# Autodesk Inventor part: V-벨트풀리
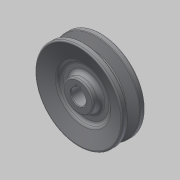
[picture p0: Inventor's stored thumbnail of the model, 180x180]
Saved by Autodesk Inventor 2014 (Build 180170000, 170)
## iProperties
Created: 2016-08
Part Number: V-벨트풀리
Material: 알루미늄 6061
Document SubType Name: Modeling
Designer: mduedu
Density: 2.71 g/cm^3
Appearance: Default
Author: mduedu
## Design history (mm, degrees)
sketch "스케치1"
  geometry: L1 (0, 9.5)-(0, -9.5); L2 (0, 9.5)-(35, 9.5); L3 (35, 9.5)-(35, 4.825); L4 (35, 4.825)-(26, 2.074); L5 (26, 2.074)-(26, 0); L6 (0, 0)-(26, 0); L7 (0, -9.5)-(35, -9.5); L8 (35, -9.5)-(35, -4.825); L9 (35, -4.825)-(26, -2.074); L10 (26, -2.074)-(26, 0); L11 (32.3, 9.5)-(32.3, -9.5); 3 further points
  constraints: 22 end point, 6 point on line, 4 perpendicular, 3 symmetric about line, 1 coincident, 1 horizontal alignment, 1 midpoint, 1 parallel, 1 vertical
  dimensions: "d0" = 19 distance of L1.start L1.end; "d2" = 70 diameter of L8 L1; "d4" = 6.3 distance between parallel lines of L10 L11; "d5" = 2.7 distance between parallel lines of L11 L8; "d6" = 8 distance of point (32.3, -4) point (32.3, 4); "d7" = 34 deg angle of L9 L4
revolve "회전1" sketch "스케치1" stored, may be unused: angle "d8" = 90 deg
sketch "스케치2"
  geometry: L1 (-2, 0)-(2, 0); L2 (2, 0)-(2, 7.8); L3 (2, 7.8)-(-2, 7.8); L4 (-2, 7.8)-(-2, 0); C1 r 6 at (0, 0); 2 further points
  constraints: 8 end point, 2 coincident, 2 parallel, 1 centre point, 1 horizontal, 1 midpoint, 1 perpendicular
  dimensions: "d9" = 12 diameter of C1; "d11" = 4 distance of L2.end L3.end; "d12" = 7.8 distance of L1.end L2.end
extrude "돌출1" cut sketch "스케치2" stored distance "d13" = 10; taper "d14" = 0 deg
sketch "스케치3"
  geometry: L1 (35, 4.825)-(26, 2.074) reference; L2 (26, 2.074)-(26, -2.074) reference; L3 (0, 0)-(26, 0); L4 (35, 9.5)-(35, 4.825) reference; L5 (-35, 9.5)-(35, 9.5) reference; L6 (35, 9.5)-(21, 5.22); L7 (21, 5.22)-(21, 3); L8 (21, 3)-(12, 3); L9 (12, 3)-(12, 9.5); L10 (0, 9.5)-(0, -9.5); L11 (5.657, -9.5)-(-6, -9.5) reference; L12 (12, 9.5)-(35, 9.5)
  constraints: 14 end point, 3 midpoint, 2 parallel, 2 perpendicular, 2 point on line, 1 collinear, 1 horizontal
  dimensions: "d15" = 3 distance between parallel lines of L3 L8; "d17" = 42 diameter of L7 L10; "d18" = 24 diameter of L9 L10
revolve "회전2" sketch "스케치3" stored, may be unused: angle "d19" = 90 deg
fillet "모깎기1" dims "d20" = 0.5, "d21" = 1, "d22" = 1
fillet "모깎기2" dims "d23" = 3
fillet "모깎기3" dims "d24" = 3
fillet "모깎기4" dims "d25" = 3
chamfer "모따기1" distance "d26" = 0.5; stored, may be unused: second distance "d27" = 2, angle "d28" = 45 deg
fillet "모깎기5" dims "d29" = 1
node "솔리드1"
mirror "대칭1"
